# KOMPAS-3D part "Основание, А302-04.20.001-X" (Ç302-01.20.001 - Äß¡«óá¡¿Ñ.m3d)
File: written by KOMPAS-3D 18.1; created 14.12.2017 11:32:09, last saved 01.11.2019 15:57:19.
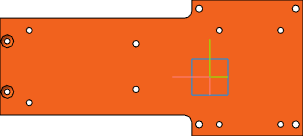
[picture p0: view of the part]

Document properties: Автор: Милов; Организация: Милов; Полное имя файла: D:\Мембранные насосы\Мембранный электропривод\А302-00.00.000 - ASTRA-302 (МЭ200)\3Д ПВХ\А302-01.20.001 - Основание.m3d

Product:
- Part/product: Основание  | designation А302-04.20.001-X
    Материал: Сталь 20  ГОСТ 1050-2013 (density 7820 kg/m3)
    Масса: 2.48623
    Раздел спецификации: Детали
    Форматы листов документа: A3
    source file: ..\А302-04.00.000 - Мембранный насос ASTRA-302-PP\А302-04.20.001 - Основание.cdw
- Part/product: Основание  | designation А302-04.20.001
    Материал: Сталь 20  ГОСТ 1050-2013 (density 7820 kg/m3)
    Масса: 2.48623
    Раздел спецификации: Детали
    Форматы листов документа: A3
- Part/product: Основание  | designation А302-01.20.001
    Материал: Сталь 20  ГОСТ 1050-2013 (density 7820 kg/m3)
    Масса: 2.48169
    Раздел спецификации: Детали
    Форматы листов документа: A3
    source file: ..\А302-04.00.000 - Мембранный насос ASTRA-302-PP\А302-04.20.001 - Основание.cdw, А302-01.20.001 - Основание.cdw

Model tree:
1. Эскиз:1
2. Листовое тело:1
     Расстояние 1 = 10; Радиус сгиба = 5
3. Эскиз:8  (with: Листовое тело:1)
4. Вырез в листовом теле:1
     Глубина выреза = 10
5. Эскиз:9  (with: Листовое тело:1)
6. Операция выдавливания:1
     Расстояние 1 = 25
7. Эскиз:10  (with: Листовое тело:1)
8. Операция выдавливания:2
     Расстояние 1 = 25
9. Эскиз:11  (with: Листовое тело:1)
10. Операция выдавливания:3
     Расстояние 1 = 25
11. Эскиз:12  (with: Листовое тело:1, Операция выдавливания:2, Операция выдавливания:3)
12. Операция выдавливания:4
     Расстояние 1 = 25
13. Эскиз:13  (with: Листовое тело:1)
14. Вырезать элемент выдавливания:1
     Расстояние 1 = 30
15. Фаска:1  (with: Вырезать элемент выдавливания:1)
     Угол = 45; Длина 1 = 5; Длина 2 = 5
16. Массив по сетке:1  (with: Вырезать элемент выдавливания:1, Эскиз:13, Фаска:1)  (2 pattern instances)
     Шаг 1 = 120; Угол раствора = -90; Шаг 2 = 70; Геометрический массив = 128
17. Эскиз:14  (with: Листовое тело:1)
18. Вырезать элемент выдавливания:2
     Расстояние 1 = 30
19. Массив по сетке:2  (with: Вырезать элемент выдавливания:2, Эскиз:14)  (4 pattern instances)
     Наклон = 180; Шаг 1 = 134; Угол раствора = 90; Шаг 2 = 160; Геометрический массив = 128
20. Скругление:1  (with: Операция выдавливания:3, Операция выдавливания:4)  (labels: Сталь 20  ГОСТ 1050-2013; Отработка\А302-01.20.000 - Мотор-редуктор.a3d)
     Радиус = 10

Expressions: 26+3; 250+16
Referenced files in D:\Мембранные насосы\Мембранный электропривод\А302-00.00.000 - ASTRA-302 (МЭ200)\3Д ПВХ\Отработка\: А302-01.20.000 - Мотор-редуктор.a3d
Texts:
  Фланец\Труба 140х140х6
